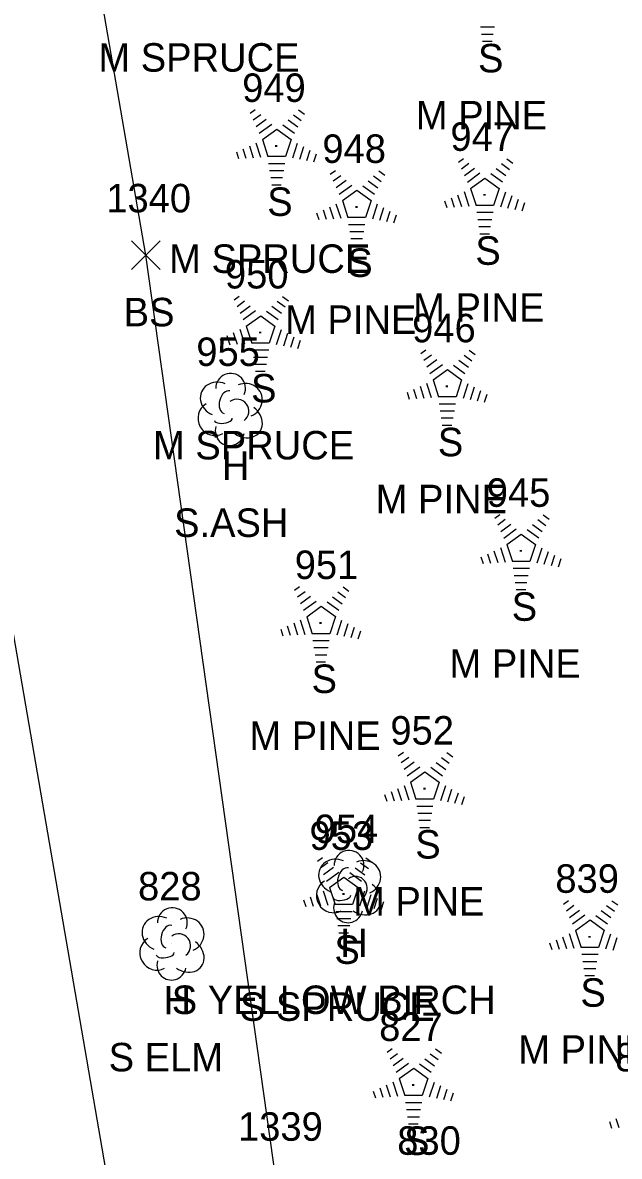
# Model space of a CAD drawing. Extents: x 1545627 to 1546562, y 571176 to 576667.
# Drawn here: x 1546104.7 to 1546146.5, y 572314.1 to 572393.7 of the extents above; entities that cross this region are included whole.
import ezdxf

# ---------------------------------------------------------------- set-up
doc = ezdxf.new("R2010")
doc.units = 0
for name, color, linetype in [('L_A', 7, 'Continuous'), ('L_C', 7, 'Continuous'), ('L_I', 7, 'Continuous'), ('L_TIC', 7, 'Continuous'), ('LAWA', 7, 'Continuous'), ('LELB', 7, 'Continuous'), ('LTC', 7, 'Continuous'), ('LTD', 7, 'Continuous')]:
    doc.layers.add(name, color=color, linetype=linetype)

msp = doc.modelspace()

# ---------------------------------------------------------------- linework, layer by layer
at = {"layer": 'L_TIC'}
for points in [[(1546112.316, 572376.356), (1546114.316, 572378.356)], [(1546114.316, 572376.356), (1546112.316, 572378.356)]]:
    msp.add_lwpolyline(points, dxfattribs=at)
at = {"layer": 'LAWA'}
msp.add_lwpolyline([(1546132.696, 572194.892), (1546123.453, 572251.154), (1546111.937, 572304.897), (1546099.961, 572374.277), (1546086.111, 572421.028), (1546079.849, 572451.625), (1546071.905, 572496.172), (1546064.394, 572527.582), (1546058.594, 572548.653), (1546052.091, 572585.928), (1546038.425, 572619.665), (1546027.83, 572654.921), (1546018.77, 572685.669), (1546005.342, 572728.46), (1545993.814, 572765.207), (1545980.931, 572799.992)], dxfattribs=at)
at = {"layer": 'LELB'}
msp.add_lwpolyline([(1546138.092, 572206.647), (1546133.659, 572247.148), (1546122.485, 572312.188), (1546113.316, 572377.356), (1546104.81, 572426.631), (1546099.996, 572460.654), (1546092.988, 572497.654), (1546081.836, 572529.538), (1546071.729, 572550.604), (1546058.937, 572584.302), (1546058.009, 572591.614), (1546041.849, 572621.011), (1546036.285, 572644.955)], dxfattribs=at)
at = {"layer": 'LTC'}
for p, q in [((1546137.785, 572393.346), (1546136.797, 572393.346)), ((1546137.701, 572392.846), (1546136.87, 572392.846)), ((1546137.618, 572392.346), (1546136.943, 572392.346)), ((1546120.641, 572387.316), (1546120.996, 572387.573)), ((1546124.039, 572387.556), (1546124.458, 572387.252)), ((1546120.851, 572386.85), (1546121.38, 572387.234)), ((1546121.06, 572386.384), (1546121.764, 572386.896)), ((1546123.297, 572386.859), (1546123.976, 572386.366)), ((1546123.668, 572387.208), (1546124.218, 572386.809)), ((1546121.27, 572385.919), (1546122.148, 572386.557)), ((1546121.494, 572385.464), (1546122.506, 572386.198)), ((1546122.506, 572386.198), (1546123.503, 572385.473)), ((1546122.926, 572386.511), (1546123.736, 572385.922)), ((1546120.584, 572385.028), (1546120.856, 572384.193)), ((1546121.04, 572385.244), (1546121.371, 572384.225)), ((1546121.494, 572385.464), (1546121.881, 572384.27)), ((1546123.503, 572385.473), (1546123.112, 572384.27)), ((1546123.941, 572385.202), (1546123.603, 572384.163)), ((1546119.674, 572384.595), (1546119.826, 572384.127)), ((1546120.129, 572384.812), (1546120.341, 572384.16)), ((1546123.112, 572384.27), (1546121.881, 572384.27)), ((1546124.385, 572384.952), (1546124.098, 572384.067)), ((1546124.83, 572384.702), (1546124.593, 572383.972)), ((1546125.274, 572384.452), (1546125.087, 572383.877)), ((1546123.073, 572383.77), (1546121.929, 572383.77)), ((1546135.249, 572383.884), (1546135.604, 572384.141)), ((1546135.459, 572383.418), (1546135.988, 572383.802)), ((1546135.669, 572382.952), (1546136.372, 572383.464)), ((1546138.276, 572383.776), (1546138.826, 572383.377)), ((1546138.648, 572384.124), (1546139.067, 572383.819)), ((1546122.99, 572383.27), (1546122.001, 572383.27)), ((1546122.906, 572382.77), (1546122.074, 572382.77)), ((1546126.26, 572383.034), (1546126.615, 572383.292)), ((1546126.47, 572382.569), (1546126.999, 572382.953)), ((1546129.287, 572382.927), (1546129.837, 572382.527)), ((1546129.659, 572383.275), (1546130.078, 572382.97)), ((1546135.878, 572382.487), (1546136.756, 572383.124)), ((1546136.103, 572382.032), (1546137.114, 572382.766)), ((1546137.114, 572382.766), (1546138.111, 572382.041)), ((1546137.534, 572383.079), (1546138.344, 572382.49)), ((1546137.906, 572383.427), (1546138.585, 572382.934)), ((1546122.822, 572382.27), (1546122.147, 572382.27)), ((1546126.679, 572382.103), (1546127.383, 572382.614)), ((1546126.889, 572381.637), (1546127.767, 572382.275)), ((1546127.114, 572381.182), (1546128.125, 572381.917)), ((1546128.125, 572381.917), (1546129.122, 572381.192)), ((1546128.545, 572382.23), (1546129.355, 572381.641)), ((1546128.916, 572382.578), (1546129.596, 572382.084)), ((1546136.103, 572382.032), (1546136.49, 572380.838)), ((1546138.111, 572382.041), (1546137.72, 572380.838)), ((1546127.114, 572381.182), (1546127.501, 572379.989)), ((1546129.122, 572381.192), (1546128.731, 572379.989)), ((1546134.282, 572381.163), (1546134.434, 572380.695)), ((1546134.737, 572381.379), (1546134.949, 572380.728)), ((1546135.193, 572381.596), (1546135.464, 572380.761)), ((1546135.648, 572381.812), (1546135.979, 572380.793)), ((1546138.549, 572381.77), (1546138.211, 572380.731)), ((1546138.994, 572381.52), (1546138.706, 572380.635)), ((1546139.438, 572381.27), (1546139.201, 572380.54)), ((1546125.293, 572380.314), (1546125.445, 572379.846)), ((1546125.748, 572380.53), (1546125.96, 572379.879)), ((1546126.204, 572380.747), (1546126.475, 572379.912)), ((1546126.659, 572380.963), (1546126.99, 572379.944)), ((1546129.56, 572380.921), (1546129.222, 572379.882)), ((1546130.004, 572380.671), (1546129.717, 572379.786)), ((1546130.449, 572380.421), (1546130.212, 572379.691)), ((1546137.72, 572380.838), (1546136.49, 572380.838)), ((1546137.682, 572380.338), (1546136.537, 572380.338)), ((1546139.882, 572381.019), (1546139.696, 572380.445)), ((1546128.731, 572379.989), (1546127.501, 572379.989)), ((1546128.693, 572379.489), (1546127.548, 572379.489)), ((1546130.893, 572380.17), (1546130.706, 572379.596)), ((1546137.598, 572379.838), (1546136.61, 572379.838)), ((1546128.609, 572378.989), (1546127.621, 572378.989)), ((1546137.514, 572379.338), (1546136.683, 572379.338)), ((1546137.431, 572378.838), (1546136.756, 572378.838)), ((1546128.525, 572378.489), (1546127.694, 572378.489)), ((1546128.441, 572377.989), (1546127.766, 572377.989)), ((1546119.508, 572374.222), (1546119.863, 572374.479)), ((1546119.718, 572373.756), (1546120.247, 572374.141)), ((1546122.535, 572374.114), (1546123.085, 572373.715)), ((1546122.907, 572374.462), (1546123.326, 572374.158)), ((1546119.927, 572373.291), (1546120.631, 572373.802)), ((1546120.137, 572372.825), (1546121.015, 572373.463)), ((1546120.362, 572372.37), (1546121.373, 572373.104)), ((1546121.373, 572373.104), (1546122.37, 572372.379)), ((1546121.793, 572373.417), (1546122.603, 572372.828)), ((1546122.164, 572373.766), (1546122.844, 572373.272)), ((1546120.362, 572372.37), (1546120.749, 572371.176)), ((1546122.37, 572372.379), (1546121.979, 572371.176)), ((1546118.541, 572371.501), (1546118.693, 572371.033)), ((1546118.996, 572371.718), (1546119.208, 572371.066)), ((1546119.452, 572371.934), (1546119.723, 572371.099)), ((1546119.907, 572372.151), (1546120.238, 572371.131)), ((1546122.808, 572372.108), (1546122.47, 572371.069)), ((1546123.252, 572371.858), (1546122.965, 572370.973)), ((1546123.697, 572371.608), (1546123.46, 572370.878)), ((1546121.979, 572371.176), (1546120.749, 572371.176)), ((1546124.141, 572371.358), (1546123.954, 572370.783)), ((1546132.617, 572370.445), (1546132.972, 572370.702)), ((1546121.941, 572370.676), (1546120.796, 572370.676)), ((1546121.857, 572370.176), (1546120.869, 572370.176)), ((1546132.827, 572369.979), (1546133.356, 572370.363)), ((1546133.036, 572369.513), (1546133.74, 572370.025)), ((1546135.273, 572369.988), (1546135.953, 572369.495)), ((1546135.644, 572370.337), (1546136.194, 572369.937)), ((1546136.015, 572370.685), (1546136.435, 572370.38)), ((1546121.773, 572369.676), (1546120.942, 572369.676)), ((1546121.689, 572369.176), (1546121.014, 572369.176)), ((1546133.246, 572369.047), (1546134.124, 572369.685)), ((1546133.47, 572368.592), (1546134.482, 572369.327)), ((1546134.482, 572369.327), (1546135.479, 572368.602)), ((1546134.902, 572369.64), (1546135.712, 572369.051)), ((1546133.016, 572368.373), (1546133.347, 572367.354)), ((1546133.47, 572368.592), (1546133.858, 572367.399)), ((1546135.479, 572368.602), (1546135.088, 572367.399)), ((1546135.917, 572368.331), (1546135.579, 572367.292)), ((1546131.65, 572367.724), (1546131.802, 572367.256)), ((1546132.105, 572367.94), (1546132.317, 572367.289)), ((1546132.56, 572368.157), (1546132.832, 572367.322)), ((1546136.361, 572368.081), (1546136.074, 572367.196)), ((1546136.806, 572367.831), (1546136.569, 572367.101)), ((1546137.25, 572367.58), (1546137.063, 572367.006)), ((1546135.088, 572367.399), (1546133.858, 572367.399)), ((1546135.05, 572366.899), (1546133.905, 572366.899)), ((1546134.966, 572366.399), (1546133.978, 572366.399)), ((1546134.882, 572365.899), (1546134.05, 572365.899)), ((1546134.798, 572365.399), (1546134.123, 572365.399)), ((1546137.8, 572358.895), (1546138.155, 572359.153)), ((1546138.01, 572358.43), (1546138.539, 572358.814)), ((1546140.827, 572358.787), (1546141.377, 572358.388)), ((1546141.199, 572359.136), (1546141.618, 572358.831)), ((1546138.219, 572357.964), (1546138.923, 572358.475)), ((1546138.429, 572357.498), (1546139.307, 572358.136)), ((1546140.085, 572358.091), (1546140.895, 572357.502)), ((1546140.456, 572358.439), (1546141.136, 572357.945)), ((1546138.654, 572357.043), (1546139.665, 572357.778)), ((1546139.665, 572357.778), (1546140.662, 572357.053)), ((1546137.288, 572356.391), (1546137.5, 572355.74)), ((1546137.744, 572356.608), (1546138.015, 572355.772)), ((1546138.199, 572356.824), (1546138.53, 572355.805)), ((1546138.654, 572357.043), (1546139.041, 572355.85)), ((1546140.662, 572357.053), (1546140.271, 572355.85)), ((1546141.1, 572356.782), (1546140.762, 572355.742)), ((1546141.544, 572356.532), (1546141.257, 572355.647)), ((1546136.833, 572356.175), (1546136.985, 572355.707)), ((1546140.271, 572355.85), (1546139.041, 572355.85)), ((1546141.989, 572356.282), (1546141.752, 572355.552)), ((1546142.433, 572356.031), (1546142.246, 572355.457)), ((1546140.233, 572355.35), (1546139.088, 572355.35)), ((1546140.149, 572354.85), (1546139.161, 572354.85)), ((1546123.753, 572353.827), (1546124.108, 572354.085)), ((1546127.151, 572354.068), (1546127.571, 572353.763)), ((1546140.065, 572354.35), (1546139.234, 572354.35)), ((1546123.963, 572353.362), (1546124.492, 572353.746)), ((1546124.172, 572352.896), (1546124.876, 572353.407)), ((1546126.409, 572353.371), (1546127.089, 572352.877)), ((1546126.78, 572353.719), (1546127.33, 572353.32)), ((1546139.981, 572353.85), (1546139.306, 572353.85)), ((1546124.382, 572352.43), (1546125.26, 572353.068)), ((1546124.606, 572351.975), (1546125.618, 572352.71)), ((1546125.618, 572352.71), (1546126.615, 572351.985)), ((1546126.038, 572353.023), (1546126.848, 572352.434)), ((1546124.152, 572351.756), (1546124.483, 572350.737)), ((1546124.606, 572351.975), (1546124.994, 572350.782)), ((1546126.615, 572351.985), (1546126.224, 572350.782)), ((1546127.053, 572351.714), (1546126.715, 572350.674)), ((1546122.786, 572351.106), (1546122.938, 572350.639)), ((1546123.241, 572351.323), (1546123.453, 572350.671)), ((1546123.696, 572351.54), (1546123.968, 572350.704)), ((1546127.497, 572351.464), (1546127.21, 572350.579)), ((1546127.942, 572351.214), (1546127.705, 572350.484)), ((1546128.386, 572350.963), (1546128.199, 572350.389)), ((1546126.224, 572350.782), (1546124.994, 572350.782)), ((1546126.186, 572350.282), (1546125.041, 572350.282)), ((1546126.102, 572349.782), (1546125.114, 572349.782)), ((1546126.018, 572349.282), (1546125.186, 572349.282)), ((1546125.934, 572348.782), (1546125.259, 572348.782)), ((1546131.034, 572342.206), (1546131.389, 572342.464)), ((1546131.244, 572341.741), (1546131.773, 572342.125)), ((1546134.061, 572342.098), (1546134.611, 572341.699)), ((1546134.432, 572342.447), (1546134.851, 572342.142)), ((1546131.453, 572341.275), (1546132.157, 572341.786)), ((1546131.663, 572340.809), (1546132.541, 572341.447)), ((1546133.319, 572341.402), (1546134.129, 572340.813)), ((1546133.69, 572341.75), (1546134.369, 572341.256)), ((1546131.887, 572340.354), (1546132.899, 572341.089)), ((1546132.899, 572341.089), (1546133.896, 572340.364)), ((1546130.522, 572339.702), (1546130.734, 572339.05)), ((1546130.977, 572339.919), (1546131.249, 572339.083)), ((1546131.433, 572340.135), (1546131.764, 572339.116)), ((1546131.887, 572340.354), (1546132.274, 572339.161)), ((1546133.896, 572340.364), (1546133.505, 572339.161)), ((1546134.334, 572340.093), (1546133.996, 572339.053)), ((1546134.778, 572339.842), (1546134.491, 572338.958)), ((1546130.066, 572339.485), (1546130.219, 572339.017)), ((1546133.505, 572339.161), (1546132.274, 572339.161)), ((1546135.223, 572339.592), (1546134.986, 572338.863)), ((1546135.667, 572339.342), (1546135.48, 572338.768)), ((1546133.466, 572338.661), (1546132.322, 572338.661)), ((1546133.383, 572338.161), (1546132.394, 572338.161)), ((1546133.299, 572337.661), (1546132.467, 572337.661)), ((1546133.215, 572337.161), (1546132.54, 572337.161)), ((1546125.356, 572334.813), (1546125.711, 572335.071)), ((1546128.755, 572335.054), (1546129.174, 572334.749)), ((1546125.566, 572334.348), (1546126.095, 572334.732)), ((1546125.775, 572333.882), (1546126.479, 572334.393)), ((1546128.012, 572334.357), (1546128.692, 572333.863)), ((1546128.383, 572334.706), (1546128.933, 572334.306)), ((1546125.985, 572333.416), (1546126.863, 572334.054)), ((1546126.21, 572332.961), (1546127.221, 572333.696)), ((1546127.221, 572333.696), (1546128.218, 572332.971)), ((1546127.641, 572334.009), (1546128.451, 572333.42)), ((1546125.3, 572332.526), (1546125.571, 572331.691)), ((1546125.755, 572332.742), (1546126.086, 572331.723)), ((1546126.21, 572332.961), (1546126.597, 572331.768)), ((1546128.218, 572332.971), (1546127.827, 572331.768)), ((1546128.656, 572332.7), (1546128.318, 572331.661)), ((1546124.389, 572332.093), (1546124.541, 572331.625)), ((1546124.844, 572332.309), (1546125.056, 572331.658)), ((1546127.827, 572331.768), (1546126.597, 572331.768)), ((1546129.1, 572332.45), (1546128.813, 572331.565)), ((1546129.545, 572332.2), (1546129.308, 572331.47)), ((1546129.989, 572331.949), (1546129.802, 572331.375)), ((1546142.623, 572331.802), (1546142.978, 572332.06)), ((1546142.833, 572331.337), (1546143.362, 572331.721)), ((1546146.022, 572332.042), (1546146.441, 572331.738)), ((1546127.789, 572331.268), (1546126.644, 572331.268)), ((1546143.042, 572330.871), (1546143.746, 572331.382)), ((1546143.252, 572330.405), (1546144.13, 572331.043)), ((1546144.908, 572330.997), (1546145.718, 572330.409)), ((1546145.28, 572331.346), (1546145.959, 572330.852)), ((1546145.65, 572331.694), (1546146.2, 572331.295)), ((1546127.705, 572330.768), (1546126.717, 572330.768)), ((1546127.621, 572330.268), (1546126.79, 572330.268)), ((1546143.477, 572329.95), (1546144.488, 572330.685)), ((1546144.488, 572330.685), (1546145.485, 572329.96)), ((1546127.537, 572329.768), (1546126.862, 572329.768)), ((1546142.567, 572329.515), (1546142.838, 572328.679)), ((1546143.022, 572329.731), (1546143.353, 572328.712)), ((1546143.477, 572329.95), (1546143.864, 572328.757)), ((1546145.485, 572329.96), (1546145.094, 572328.757)), ((1546145.923, 572329.689), (1546145.585, 572328.649)), ((1546146.367, 572329.438), (1546146.08, 572328.554)), ((1546141.656, 572329.081), (1546141.808, 572328.613)), ((1546142.111, 572329.298), (1546142.323, 572328.646)), ((1546145.094, 572328.757), (1546143.864, 572328.757)), ((1546145.056, 572328.257), (1546143.911, 572328.257)), ((1546144.972, 572327.757), (1546143.984, 572327.757)), ((1546144.888, 572327.257), (1546144.057, 572327.257)), ((1546144.805, 572326.757), (1546144.13, 572326.757)), ((1546130.246, 572321.401), (1546130.601, 572321.658)), ((1546133.645, 572321.641), (1546134.064, 572321.336)), ((1546130.456, 572320.935), (1546130.985, 572321.319)), ((1546130.666, 572320.469), (1546131.369, 572320.981)), ((1546130.875, 572320.003), (1546131.753, 572320.641)), ((1546132.531, 572320.596), (1546133.341, 572320.007)), ((1546132.903, 572320.944), (1546133.582, 572320.451)), ((1546133.273, 572321.293), (1546133.823, 572320.893)), ((1546131.1, 572319.548), (1546132.111, 572320.283)), ((1546132.111, 572320.283), (1546133.108, 572319.558)), ((1546130.19, 572319.113), (1546130.461, 572318.278)), ((1546130.645, 572319.329), (1546130.976, 572318.31)), ((1546131.1, 572319.548), (1546131.487, 572318.355)), ((1546133.108, 572319.558), (1546132.717, 572318.355)), ((1546133.546, 572319.287), (1546133.208, 572318.248)), ((1546133.991, 572319.037), (1546133.703, 572318.152)), ((1546129.279, 572318.68), (1546129.431, 572318.212)), ((1546129.734, 572318.896), (1546129.946, 572318.245)), ((1546132.717, 572318.355), (1546131.487, 572318.355)), ((1546134.435, 572318.787), (1546134.198, 572318.057)), ((1546134.879, 572318.536), (1546134.693, 572317.962)), ((1546132.679, 572317.855), (1546131.534, 572317.855)), ((1546132.595, 572317.355), (1546131.607, 572317.355)), ((1546132.511, 572316.855), (1546131.68, 572316.855)), ((1546146.305, 572316.761), (1546146.517, 572316.109)), ((1546132.428, 572316.355), (1546131.753, 572316.355)), ((1546145.85, 572316.544), (1546146.002, 572316.077))]:
    msp.add_line(p, q, dxfattribs=at)
at = {"layer": 'LTD'}
for p, q in [((1546119.216, 572366.574), (1546119.216, 572366.574)), ((1546119.216, 572366.574), (1546119.216, 572366.574)), ((1546127.526, 572333.086), (1546127.526, 572333.086)), ((1546127.526, 572333.086), (1546127.526, 572333.086)), ((1546115.128, 572329.059), (1546115.128, 572329.059)), ((1546115.128, 572329.059), (1546115.128, 572329.059))]:
    msp.add_line(p, q, dxfattribs=at)
for centre in [(1546119.263, 572368.008), (1546127.573, 572334.52), (1546115.175, 572330.493)]:
    msp.add_arc(centre, 1.047, 335.52715, 180.95627, dxfattribs=at)
for centre, major_axis, ratio, start_param, end_param in [((1546118.425, 572367.24), (1.21, -0.512), 0.895232, 1.570796, 4.712389), ((1546120.258, 572367.157), (-1.141, -0.483), 0.949671, 1.570796, 4.712389), ((1546119.008, 572367.032), (-0.208, -0.792), 0.645439, 3.141593, 6.283185), ((1546118.133, 572365.865), (0.584, -1.042), 0.959034, 3.141593, 6.283185), ((1546119.716, 572366.407), (-0.5, 0.667), 0.989748, 3.141593, 6.283185), ((1546120.217, 572365.741), (-1.09, 0.792), 0.841452, 1.570796, 4.712389), ((1546119.217, 572365.074), (0.265, 1.061), 0.942809, 1.570796, 4.712389), ((1546118.758, 572365.824), (-0.625, -0.083), 0.423636, 0, 3.141593), ((1546126.734, 572333.752), (1.21, -0.512), 0.895232, 1.570796, 4.712389), ((1546128.568, 572333.669), (-1.141, -0.483), 0.949671, 1.570796, 4.712389), ((1546127.318, 572333.544), (-0.208, -0.792), 0.645439, 3.141593, 6.283185), ((1546126.443, 572332.377), (0.584, -1.042), 0.959034, 3.141593, 6.283185), ((1546128.026, 572332.919), (-0.5, 0.667), 0.989748, 3.141593, 6.283185), ((1546128.526, 572332.253), (-1.09, 0.792), 0.841452, 1.570796, 4.712389), ((1546127.526, 572331.586), (0.265, 1.061), 0.942809, 1.570796, 4.712389), ((1546127.068, 572332.336), (-0.625, -0.083), 0.423636, 0, 3.141593), ((1546114.337, 572329.725), (1.21, -0.512), 0.895232, 1.570796, 4.712389), ((1546116.17, 572329.642), (-1.141, -0.483), 0.949671, 1.570796, 4.712389), ((1546114.92, 572329.517), (-0.208, -0.792), 0.645439, 3.141593, 6.283185), ((1546114.045, 572328.35), (0.584, -1.042), 0.959034, 3.141593, 6.283185), ((1546115.628, 572328.892), (-0.5, 0.667), 0.989748, 3.141593, 6.283185), ((1546116.128, 572328.226), (-1.09, 0.792), 0.841452, 1.570796, 4.712389), ((1546115.129, 572327.559), (0.265, 1.061), 0.942809, 1.570796, 4.712389), ((1546114.67, 572328.309), (-0.625, -0.083), 0.423636, 0, 3.141593)]:
    msp.add_ellipse(centre, major_axis=major_axis, ratio=ratio, start_param=start_param, end_param=end_param, dxfattribs=at)

# ---------------------------------------------------------------- texts
at = {"layer": 'L_A'}
for s, p in [('S', (1546136.627, 572390.183)), ('S', (1546121.832, 572380.108)), ('S', (1546136.44, 572376.675)), ('S', (1546127.451, 572375.826)), ('BS', (1546111.757, 572372.356)), ('S', (1546120.699, 572367.014)), ('S', (1546133.808, 572363.236)), ('H', (1546118.65, 572361.574)), ('S', (1546138.991, 572351.687)), ('S', (1546124.944, 572346.619)), ('S', (1546132.225, 572334.998)), ('S', (1546126.547, 572327.605)), ('H', (1546126.959, 572328.086)), ('S', (1546143.814, 572324.594)), ('H', (1546114.561, 572324.059)), ('S', (1546131.437, 572314.192))]:
    msp.add_text(s, height=2, dxfattribs=at).set_placement(p)
at = {"layer": 'L_C'}
for s, p in [('M SPRUCE', (1546109.982, 572390.233)), ('M PINE', (1546132.265, 572386.183)), ('M SPRUCE', (1546114.95, 572376.108)), ('M PINE', (1546132.078, 572372.675)), ('M PINE', (1546123.089, 572371.826)), ('M SPRUCE', (1546113.817, 572363.014)), ('M PINE', (1546129.446, 572359.236)), ('S.ASH', (1546115.295, 572357.574)), ('M PINE', (1546134.629, 572347.687)), ('M PINE', (1546120.582, 572342.619)), ('M PINE', (1546127.862, 572330.998)), ('S YELLOW BIRCH', (1546115.132, 572324.086)), ('S SPRUCE', (1546119.917, 572323.605)), ('M PINE', (1546139.452, 572320.594)), ('S ELM', (1546110.703, 572320.059))]:
    msp.add_text(s, height=2, dxfattribs=at).set_placement(p)
at = {"layer": 'L_I'}
for s, p in [('949', (1546120.076, 572388.108)), ('947', (1546134.692, 572384.675)), ('948', (1546125.703, 572383.826)), ('1340', (1546110.537, 572380.356)), ('950', (1546118.864, 572375.014)), ('946', (1546132.005, 572371.236)), ('955', (1546116.854, 572369.574)), ('945', (1546137.243, 572359.687)), ('951', (1546123.763, 572354.619)), ('952', (1546130.477, 572342.998)), ('954', (1546125.164, 572336.086)), ('953', (1546124.799, 572335.605)), ('839', (1546142.058, 572332.594)), ('828', (1546112.766, 572332.059)), ('827', (1546129.689, 572322.192)), ('838', (1546146.26, 572320.057)), ('1339', (1546119.784, 572315.188)), ('830', (1546130.959, 572314.204))]:
    msp.add_text(s, height=2, dxfattribs=at).set_placement(p)
at = {"layer": 'LTC'}
for p in [(1546122.389, 572385.212), (1546136.997, 572381.779), (1546128.008, 572380.93), (1546121.256, 572372.118), (1546134.365, 572368.34), (1546139.548, 572356.791), (1546125.501, 572351.723), (1546132.781, 572340.102), (1546127.104, 572332.709), (1546144.371, 572329.698), (1546131.994, 572319.296)]:
    msp.add_text('.', height=1.037, rotation=270, dxfattribs=at).set_placement(p)

doc.saveas('drawing.dxf')
